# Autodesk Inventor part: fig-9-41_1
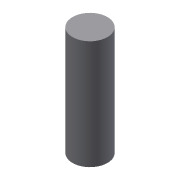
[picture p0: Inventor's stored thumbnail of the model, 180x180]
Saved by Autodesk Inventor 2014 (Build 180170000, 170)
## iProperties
Created: 2013-03
Part Number: fig-9-41_1
Material: Generic
Document SubType Name: Modeling
Designer: CADCIM
Density: 1 g/cm^3
Appearance: Default
Author: CADCIM
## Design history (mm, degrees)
sketch "Sketch1"
  geometry: C1 r 4 at (0, 0); 1 further point
  constraints: 1 centre point, 1 coincident
  dimensions: "d0" = 8 diameter of C1
extrude "Extrusion1" new body sketch "Sketch1" stored distance "d2" = 25; taper "d3" = 0 deg
body "Solid1"
